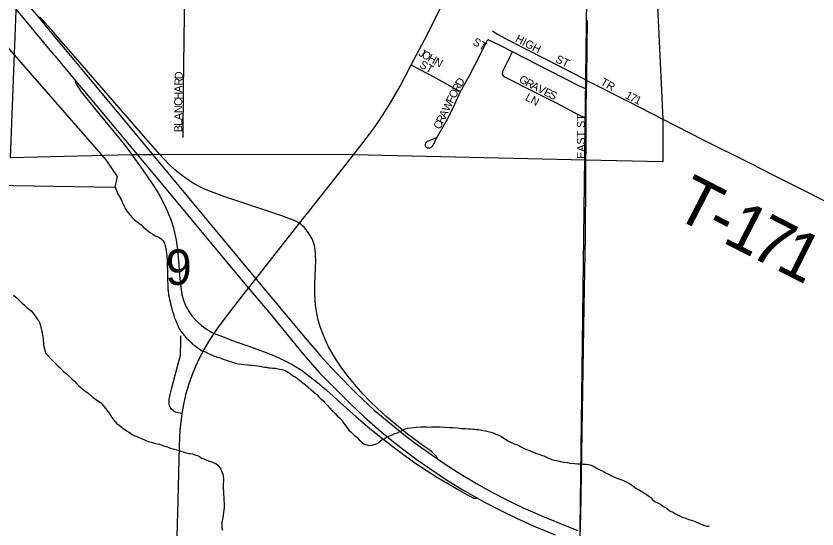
# Model space of a CAD drawing. Extents: x 1587405 to 1714697, y 1028970 to 1155083.
# Drawn here: x 1695136 to 1700142, y 1081711 to 1084915 of the extents above; entities that cross this region are included whole.
import ezdxf

# ---------------------------------------------------------------- set-up
doc = ezdxf.new("R2010")
doc.units = 0
for name, color, linetype in [('GM_X_City_Street', 7, 'Continuous'), ('GM_X_City_Street_Text', 7, 'Continuous'), ('GM_X_Corporation', 7, 'Continuous'), ('GM_X_County_Road', 7, 'Continuous'), ('GM_X_Interchange_Ramps', 7, 'Continuous'), ('GM_X_Minor_Lake', 7, 'Continuous'), ('GM_X_Minor_River', 7, 'Continuous'), ('GM_X_Section', 7, 'Continuous'), ('GM_X_Section_Text', 7, 'Continuous'), ('GM_X_State_Route', 7, 'Continuous'), ('GM_X_Township_Road', 7, 'Continuous'), ('GM_X_Township_Road_Text', 7, 'Continuous')]:
    doc.layers.add(name, color=color, linetype=linetype)

msp = doc.modelspace()

# ---------------------------------------------------------------- linework, layer by layer
at = {"layer": 'GM_X_City_Street'}
for points in [[(1696180.4, 1084157.1), (1696180.5, 1084170.3), (1696182.8, 1084453.8), (1696190.4, 1085080.3), (1696196.4, 1085475.9), (1696195.5, 1085534.4)], [(1698703, 1084513.5), (1698706.2, 1084731.8), (1698708.1, 1084887.9)], [(1698113.1, 1084823), (1698145.8, 1084802.8), (1698217.9, 1084763.1), (1698540.2, 1084598), (1698686.3, 1084522.2), (1698703, 1084513.5)], [(1697914.4, 1084443), (1697967.2, 1084539.1), (1698003.7, 1084609.4), (1698070.2, 1084740.1), (1698085.4, 1084769.4)], [(1698085.4, 1084769.4), (1698159.9, 1084733.1), (1698237.4, 1084693.7)], [(1698237.4, 1084693.7), (1698226.8, 1084668.9), (1698189.4, 1084594.8), (1698176.8, 1084568.6), (1698173.5, 1084552.6), (1698180.3, 1084541.6), (1698192.8, 1084534.1), (1698247.7, 1084506.6), (1698315.5, 1084471.7), (1698508.6, 1084374.4), (1698636.3, 1084305.8), (1698660.9, 1084293.8), (1698677.4, 1084287.3), (1698700.3, 1084283.5)], [(1698237.4, 1084693.7), (1698554.4, 1084532.3), (1698656.4, 1084479.9), (1698671.4, 1084473.2), (1698702.2, 1084459.3)], [(1697606.6, 1084609.6), (1697639.4, 1084592.7), (1697724.8, 1084548.4), (1697888.9, 1084456.7), (1697914.4, 1084443)], [(1698702.2, 1084459.3), (1698703, 1084513.5)], [(1698703, 1084513.5), (1698963.6, 1084380.9), (1699178.9, 1084270.8)], [(1698700.3, 1084283.5), (1698700.4, 1084335.3), (1698702.2, 1084459.3)], [(1697762.4, 1084153.7), (1697726.7, 1084140.2), (1697717.1, 1084136.6), (1697712.2, 1084134.4), (1697707.6, 1084132.2), (1697701.3, 1084128.3), (1697697.5, 1084124.6), (1697694.6, 1084120.1), (1697693.3, 1084115.8), (1697692.9, 1084111.5), (1697693.1, 1084108.8), (1697693.6, 1084105.6), (1697695.3, 1084101.3), (1697697, 1084098.6), (1697698.9, 1084096.9), (1697700.6, 1084095.3), (1697704, 1084093.5), (1697706.6, 1084092.4), (1697709.8, 1084091.8), (1697713.4, 1084091.2), (1697716.8, 1084091.4), (1697720.4, 1084091.8), (1697724, 1084092.9), (1697727.1, 1084094.5), (1697731.2, 1084096.6), (1697734.9, 1084099.3), (1697738.8, 1084103.5), (1697743.9, 1084110.7), (1697748.6, 1084119.5), (1697755.5, 1084134.9), (1697762.4, 1084149.2), (1697804.2, 1084221.4), (1697834.2, 1084275.3), (1697878.9, 1084364.8), (1697914.4, 1084443)], [(1698697.9, 1084015.4), (1698699.6, 1084088.6), (1698700.3, 1084283.5)]]:
    msp.add_lwpolyline(points, dxfattribs=at)
at = {"layer": 'GM_X_Corporation'}
msp.add_lwpolyline([(1695100.6, 1084030), (1695159.1, 1085548.1), (1695169.3, 1086080.7), (1695745, 1086055.9), (1698724.8, 1086009.9), (1699194.3, 1086004.2), (1699195.9, 1085349.8), (1699127.9, 1085331.6), (1699178.9, 1084270.8), (1699178, 1084003.9), (1698697.9, 1084015.4), (1697244.3, 1084048.6), (1696034.7, 1084049.8), (1695991.7, 1084048.9), (1695895, 1084048.9), (1695860.2, 1084049.1)], close=True, dxfattribs=at)
at = {"layer": 'GM_X_County_Road'}
for points in [[(1696156, 1082765.5), (1696159.4, 1082777.6), (1696161.8, 1082786.6), (1696162.9, 1082792.4), (1696163.8, 1082798.2), (1696164.3, 1082804.1), (1696164.5, 1082809.6), (1696164.8, 1082822.1), (1696165.6, 1082865.6), (1696165.9, 1082918.1)], [(1696175.2, 1082432.7), (1696176.9, 1082444.7), (1696188.5, 1082509.4), (1696200.2, 1082557.4), (1696218.8, 1082620.6), (1696240.6, 1082682.8), (1696259.3, 1082728.6), (1696280.3, 1082773.4), (1696311.4, 1082831.5), (1696345.3, 1082888), (1696374.8, 1082932.7)], [(1696175.2, 1082432.7), (1696168.4, 1082433.6), (1696150.1, 1082436), (1696137.6, 1082438.7), (1696132.1, 1082440.7), (1696127.1, 1082443.4), (1696117.1, 1082451), (1696108.4, 1082459.4), (1696100.2, 1082471.9), (1696095.8, 1082483.4), (1696093.5, 1082493.6), (1696092.4, 1082502.4), (1696092.4, 1082510.9), (1696093.8, 1082521.7), (1696095.1, 1082529.7), (1696100, 1082552.1), (1696110.3, 1082593.9), (1696152.2, 1082752.1), (1696156, 1082765.5)], [(1696145.7, 1081751.5), (1696146.7, 1081804.2), (1696157.3, 1082231.4), (1696162.9, 1082330.3), (1696167.9, 1082379.5), (1696175.2, 1082432.7)], [(1696122.9, 1080762.8), (1696130.6, 1081065.7), (1696140, 1081459.5), (1696145.7, 1081751.5)]]:
    msp.add_lwpolyline(points, dxfattribs=at)
at = {"layer": 'GM_X_Interchange_Ramps'}
for points in [[(1696908.4, 1083620.7), (1696884.3, 1083633.6), (1696870, 1083640), (1696852.4, 1083647.3), (1696797.1, 1083668.3), (1696728.6, 1083691), (1696528.9, 1083756.1), (1696435.7, 1083787.8), (1696373.9, 1083810.2), (1696325.2, 1083830), (1696289.5, 1083846.5), (1696248.9, 1083868.1), (1696207.3, 1083894.4), (1696167.5, 1083923.4), (1696129.5, 1083954.8), (1696095.8, 1083986.1), (1696059, 1084023.6), (1696034.7, 1084049.8), (1695948.1, 1084149.9), (1695601.5, 1084548.8), (1695551.8, 1084605.6), (1695418.5, 1084759.3), (1695370.4, 1084814.8), (1695299.6, 1084894), (1695293.2, 1084900.5), (1695289.9, 1084903.5), (1695287.9, 1084904.8), (1695286.3, 1084905.5), (1695285.1, 1084906), (1695283.9, 1084906.3), (1695282.9, 1084906.5), (1695281.6, 1084906.6), (1695279.9, 1084906.6), (1695278.1, 1084906.3)], [(1697769.3, 1082150.1), (1697769.1, 1082152.1), (1697768.7, 1082155.3), (1697768.1, 1082157.4), (1697767.5, 1082159.1), (1697766.9, 1082160.4), (1697766, 1082161.7), (1697765.3, 1082162.8), (1697763.8, 1082164.6), (1697754.5, 1082174.2), (1697742.9, 1082185.2), (1697732.6, 1082194.2), (1697710.1, 1082211.1), (1697691.7, 1082224.5), (1697655.5, 1082249.2), (1697572.7, 1082312.5), (1697511.3, 1082361.8), (1697448.8, 1082414.8), (1697395.3, 1082463.2), (1697348.2, 1082508.8), (1697305.1, 1082553.9), (1697261.7, 1082603), (1697212, 1082664.1), (1697172.7, 1082716.5), (1697139.3, 1082765.3), (1697110, 1082812.7), (1697089.4, 1082850), (1697069.3, 1082891.3), (1697050.6, 1082936.7), (1697037.7, 1082974), (1697025.1, 1083018.1), (1697015.8, 1083059.7), (1697008.1, 1083108.3), (1697004.8, 1083144.1), (1697002.9, 1083180.1), (1697003.8, 1083245.7), (1697007.9, 1083340.8), (1697009.6, 1083383.5), (1697008.7, 1083426.2), (1697006.3, 1083452.2), (1697001, 1083481.2), (1696993.2, 1083506.2), (1696986, 1083524.4), (1696975.3, 1083544.7), (1696962.9, 1083564.1), (1696946.8, 1083584.8), (1696936, 1083596.9), (1696927.4, 1083605.2), (1696914.6, 1083616.5), (1696908.4, 1083620.7)], [(1696374.8, 1082932.7), (1696427.5, 1082912.6), (1696483.5, 1082891.2), (1696573, 1082859), (1696693.4, 1082815.2), (1696760.4, 1082788.5), (1696814.2, 1082764), (1696866.4, 1082736.4), (1696919.4, 1082703.4), (1696974.9, 1082662.6), (1697020.8, 1082625.3), (1697075.8, 1082578.6), (1697262.3, 1082412.8), (1697346.8, 1082339.9), (1697425.5, 1082275.5), (1697490.9, 1082225.8), (1697574.1, 1082164.3), (1697641.8, 1082116.5), (1697771.1, 1082033.6), (1697848.7, 1081986.8), (1697908.9, 1081951.8), (1697963.6, 1081920.9), (1697974.8, 1081915.3), (1697989.6, 1081908), (1697992.4, 1081906.7), (1697995.4, 1081905.3), (1697998.1, 1081904.2), (1698000.8, 1081903.5), (1698003.7, 1081903.2), (1698006.3, 1081903.4), (1698008.5, 1081903.6), (1698011.9, 1081904.3), (1698016.6, 1081905.8)]]:
    msp.add_lwpolyline(points, dxfattribs=at)
at = {"layer": 'GM_X_Minor_Lake'}
for points in [[(1694980.9, 1084838.6), (1694991.3, 1083858), (1695756.4, 1083847)], [(1695756.4, 1083847), (1695769.3, 1083913), (1695698.4, 1084018.1), (1694980.9, 1084838.6)], [(1694980.9, 1084838.6), (1694991.3, 1083858), (1695756.4, 1083847), (1695769.3, 1083913), (1695698.4, 1084018.1), (1694980.9, 1084838.6)]]:
    msp.add_lwpolyline(points, dxfattribs=at)
at = {"layer": 'GM_X_Minor_River'}
for points in [[(1695756.4, 1083847), (1695764.2, 1083824.9), (1695770, 1083806.8), (1695779.8, 1083790.6), (1695787.7, 1083780.5), (1695793.6, 1083770.4), (1695797.5, 1083758.3), (1695803.3, 1083744.2), (1695811.1, 1083730.1), (1695819, 1083713.9), (1695830.7, 1083693.8), (1695846.5, 1083673.5), (1695862.4, 1083657.3), (1695876.2, 1083643.1), (1695894.1, 1083628.9), (1695904, 1083620.7), (1695917.9, 1083610.5), (1695929.8, 1083598.4), (1695945.7, 1083586.1), (1695955.6, 1083578), (1695967.5, 1083567.8), (1695977.4, 1083561.7), (1695991.4, 1083553.5), (1696005.3, 1083543.3), (1696017.2, 1083539.2), (1696029.2, 1083535), (1696043.1, 1083522.8), (1696053, 1083512.7), (1696064.8, 1083496.5), (1696066.7, 1083486.5), (1696070.5, 1083474.4), (1696072.4, 1083460.3), (1696074.3, 1083450.3), (1696077.9, 1083418.2), (1696077.8, 1083408.1), (1696079.6, 1083398.1), (1696081.5, 1083384), (1696081.3, 1083370), (1696081.1, 1083352), (1696082.9, 1083333.9), (1696082.6, 1083311.8), (1696082.3, 1083281.8), (1696082, 1083261.7), (1696083.8, 1083239.6), (1696085.6, 1083221.6), (1696085.4, 1083209.5), (1696087.2, 1083195.5), (1696089.1, 1083181.4), (1696089, 1083171.4), (1696092.8, 1083159.3), (1696094.7, 1083145.3), (1696098.5, 1083129.2), (1696104.3, 1083109.1), (1696108.1, 1083095), (1696111.9, 1083076.9), (1696115.7, 1083064.8), (1696119.6, 1083054.8), (1696125.4, 1083034.6), (1696133.2, 1083018.5), (1696137.1, 1083006.4), (1696142.9, 1082992.3), (1696148.7, 1082976.2), (1696158.5, 1082958.1), (1696166.4, 1082947.9), (1696176.3, 1082933.8), (1696188.1, 1082917.6), (1696202, 1082903.4), (1696215.8, 1082891.2), (1696227.7, 1082879), (1696239.6, 1082864.9), (1696253.5, 1082856.7), (1696265.4, 1082846.5), (1696281.3, 1082836.3), (1696297.2, 1082824.1), (1696321.2, 1082817.8), (1696339.1, 1082807.6), (1696357, 1082799.3), (1696376.9, 1082791.1), (1696394.9, 1082784.8), (1696410.9, 1082780.6), (1696424.8, 1082774.5), (1696468.7, 1082759.9), (1696482.7, 1082755.7), (1696506.6, 1082747.4), (1696524.6, 1082743.2), (1696544.6, 1082741), (1696560.6, 1082738.8), (1696582.6, 1082736.5), (1696598.6, 1082734.3), (1696612.7, 1082734.2), (1696628.7, 1082732), (1696644.7, 1082729.8), (1696662.7, 1082727.6), (1696676.6, 1082723.4), (1696688.6, 1082721.2), (1696700.7, 1082721.1), (1696714.6, 1082718.9), (1696726.7, 1082718.8), (1696738.7, 1082716.6), (1696756.7, 1082716.4), (1696774.7, 1082712.2)], [(1695119.3, 1083170.8), (1695143.1, 1083152.4), (1695157, 1083138.2), (1695172.8, 1083124), (1695188.7, 1083109.8), (1695206.5, 1083093.5), (1695220.4, 1083081.3), (1695232.3, 1083071.2), (1695248.1, 1083052.9), (1695261.9, 1083032.7), (1695269.8, 1083020.6), (1695277.6, 1083010.5), (1695283.5, 1083000.4), (1695287.4, 1082988.3), (1695291.2, 1082972.2), (1695295, 1082954.1), (1695298.8, 1082934.1), (1695304.5, 1082911.9), (1695306.3, 1082891.9), (1695308, 1082869.8), (1695309.8, 1082851.7), (1695313.6, 1082835.6), (1695317.5, 1082821.6), (1695323.3, 1082807.4), (1695335.2, 1082795.3), (1695353, 1082775), (1695396.5, 1082730.4), (1695414.4, 1082716.1), (1695432.2, 1082695.9), (1695452, 1082679.6), (1695469.8, 1082663.4), (1695487.7, 1082647.1), (1695503.5, 1082632.9), (1695515.4, 1082618.7), (1695529.2, 1082604.5), (1695541.1, 1082594.3), (1695555, 1082582.2), (1695568.9, 1082572), (1695584.8, 1082561.8), (1695598.7, 1082549.6), (1695618.5, 1082533.3), (1695634.4, 1082521.1), (1695652.3, 1082508.8), (1695666.2, 1082498.6), (1695680, 1082482.4), (1695695.8, 1082464.2), (1695709.7, 1082446), (1695723.4, 1082425.8), (1695735.2, 1082407.6), (1695747.1, 1082391.4), (1695756.9, 1082379.3), (1695766.8, 1082369.1), (1695778.8, 1082361), (1695790.7, 1082350.8), (1695806.6, 1082338.6), (1695826.4, 1082324.3), (1695844.3, 1082314.1), (1695862.2, 1082301.8), (1695878.1, 1082293.6)], [(1696774.7, 1082712.2), (1696786.7, 1082710.1), (1696798.7, 1082707.9), (1696810.6, 1082703.8), (1696826.6, 1082697.6), (1696836.5, 1082691.4), (1696848.5, 1082683.3), (1696864.3, 1082671), (1696880.2, 1082660.8), (1696896.1, 1082650.6), (1696910, 1082638.4), (1696927.9, 1082624.2), (1696945.8, 1082611.9), (1696961.6, 1082597.7), (1696979.5, 1082581.5), (1696995.3, 1082567.2), (1697015.2, 1082551), (1697029, 1082536.8), (1697040.9, 1082524.6), (1697054.8, 1082514.4), (1697066.6, 1082498.2), (1697082.5, 1082482), (1697098.3, 1082465.8), (1697112.1, 1082449.6), (1697130, 1082433.3), (1697143.8, 1082417.1), (1697157.7, 1082404.9), (1697173.5, 1082388.7), (1697183.4, 1082374.6), (1697216.9, 1082328.1), (1697228.8, 1082317.9), (1697240.6, 1082305.7), (1697252.5, 1082295.6), (1697268.4, 1082283.3), (1697280.2, 1082267.1), (1697290.2, 1082259), (1697302.1, 1082248.8), (1697312, 1082240.7), (1697333.9, 1082234.4), (1697347.9, 1082232.3), (1697362, 1082234.1), (1697382.1, 1082241.9), (1697392.2, 1082245.8), (1697408.3, 1082255.6), (1697424.5, 1082269.5), (1697434.6, 1082273.3), (1697444.7, 1082281.3), (1697456.8, 1082287.1), (1697470.9, 1082293), (1697487, 1082298.8), (1697501.1, 1082306.7), (1697521.2, 1082312.4), (1697535.3, 1082320.3), (1697547.4, 1082326.2), (1697559.5, 1082332), (1697569.6, 1082335.9), (1697585.7, 1082341.8), (1697603.7, 1082343.6), (1697621.8, 1082345.3), (1697639.8, 1082347.1), (1697665.9, 1082348.8), (1697685.9, 1082348.6), (1697701.9, 1082348.4), (1697716, 1082348.2), (1697732, 1082350.1), (1697748, 1082349.9), (1697768.1, 1082349.6), (1697786.1, 1082349.4), (1697846.1, 1082344.7), (1697868.2, 1082344.5), (1697898.2, 1082342.1), (1697918.2, 1082339.9), (1697934.2, 1082339.7), (1697948.3, 1082339.5), (1697964.3, 1082337.3), (1697976.3, 1082337.2), (1697990.3, 1082335), (1698002.3, 1082334.9), (1698014.3, 1082332.7), (1698026.3, 1082332.6), (1698038.3, 1082330.4), (1698056.3, 1082326.2), (1698070.3, 1082324), (1698086.3, 1082319.8), (1698104.2, 1082315.6), (1698118.2, 1082311.4), (1698134.1, 1082303.2), (1698154.1, 1082297), (1698170, 1082288.8), (1698183.9, 1082278.6), (1698197.9, 1082270.4), (1698213.8, 1082260.2), (1698229.7, 1082252), (1698249.6, 1082243.7), (1698263.6, 1082239.6), (1698273.6, 1082235.4), (1698283.6, 1082231.3), (1698293.5, 1082225.2), (1698307.4, 1082217), (1698327.4, 1082208.7), (1698341.3, 1082202.6)], [(1695878.1, 1082293.6), (1695890.1, 1082289.5), (1695900.1, 1082285.4), (1695920, 1082277.1), (1695943.9, 1082266.8), (1695961.9, 1082258.6), (1695981.8, 1082254.3), (1696001.8, 1082248.1), (1696017.8, 1082243.9), (1696031.8, 1082241.7), (1696043.8, 1082237.6), (1696057.7, 1082231.4), (1696071.7, 1082227.2), (1696083.7, 1082225.1), (1696095.6, 1082218.9), (1696109.6, 1082214.7), (1696123.6, 1082210.6), (1696153.5, 1082202.2), (1696165.5, 1082198), (1696181.5, 1082193.8), (1696197.4, 1082187.6), (1696215.4, 1082183.4), (1696227.4, 1082183.3), (1696239.4, 1082181.1), (1696253.4, 1082174.9), (1696269.3, 1082170.7), (1696285.3, 1082162.5), (1696295.2, 1082154.4), (1696305.2, 1082152.3), (1696317.1, 1082146.1), (1696329.1, 1082142), (1696345.1, 1082135.8), (1696359, 1082131.6), (1696369, 1082127.5), (1696385, 1082121.3), (1696396.8, 1082109.1), (1696408.7, 1082096.9), (1696416.6, 1082084.8), (1696422.4, 1082068.7), (1696428.2, 1082054.6), (1696430, 1082038.5), (1696431.9, 1082026.5), (1696431.7, 1082008.4), (1696431.5, 1081994.4), (1696431.4, 1081982.4), (1696431.2, 1081968.3), (1696432.9, 1081940.2), (1696432.7, 1081926.2), (1696434.5, 1081912.1), (1696434.4, 1081902.1), (1696434.3, 1081888.1), (1696436.1, 1081874), (1696435.9, 1081860), (1696437.7, 1081843.9), (1696435.5, 1081827.9), (1696433.4, 1081813.9), (1696431.2, 1081797.9), (1696429, 1081783.9), (1696426.9, 1081771.9), (1696422.6, 1081753.9), (1696422.5, 1081741.9), (1696422.3, 1081729.8), (1696422.2, 1081717.8), (1696426, 1081703.7)], [(1698341.3, 1082202.6), (1698353.2, 1082196.4), (1698367.2, 1082190.2), (1698383.2, 1082184), (1698403.1, 1082177.8), (1698419.1, 1082171.6), (1698435, 1082167.4), (1698447, 1082161.2), (1698458.9, 1082155.1), (1698470.9, 1082150.9), (1698484.9, 1082144.7), (1698500.8, 1082140.5), (1698512.8, 1082138.4), (1698524.8, 1082136.2), (1698538.8, 1082132.1), (1698558.8, 1082127.8), (1698582.8, 1082125.5), (1698596.8, 1082123.4), (1698626.8, 1082121), (1698644.8, 1082118.8), (1698660.9, 1082118.6), (1698678.9, 1082116.4), (1698698.9, 1082116.1), (1698714.9, 1082113.9), (1698730.9, 1082109.7), (1698746.8, 1082101.5), (1698764.7, 1082091.3), (1698784.6, 1082081), (1698804.6, 1082072.8), (1698820.5, 1082062.6), (1698838.4, 1082054.3), (1698854.3, 1082046.1), (1698864.3, 1082042), (1698876.2, 1082035.9), (1698890.2, 1082027.7), (1698916.1, 1082019.3), (1698932.1, 1082013.1), (1698950, 1082004.9), (1698963.9, 1081996.7), (1698981.8, 1081986.5), (1698995.8, 1081978.3), (1699009.6, 1081966.1), (1699025.6, 1081957.9), (1699037.5, 1081951.8), (1699047.5, 1081945.6), (1699059.4, 1081937.5), (1699075.3, 1081929.2), (1699085.2, 1081921.1), (1699095.2, 1081915), (1699103.1, 1081904.9), (1699116.9, 1081890.7), (1699132.8, 1081880.4), (1699150.8, 1081872.2), (1699166.7, 1081864), (1699182.6, 1081851.8), (1699198.5, 1081843.6), (1699210.4, 1081835.4), (1699224.3, 1081823.2), (1699242.3, 1081817), (1699254.2, 1081808.8), (1699270.1, 1081798.6), (1699284, 1081792.5), (1699300, 1081784.2), (1699313.9, 1081780.1), (1699329.9, 1081773.9), (1699341.9, 1081769.7), (1699369.8, 1081761.4), (1699383.8, 1081755.2), (1699399.7, 1081749), (1699417.7, 1081740.8), (1699433.6, 1081734.6), (1699445.6, 1081730.4), (1699455.6, 1081728.3), (1699467.6, 1081726.1), (1699455.6, 1081728.3), (1699467.6, 1081726.1)]]:
    msp.add_lwpolyline(points, dxfattribs=at)
at = {"layer": 'GM_X_Section'}
msp.add_lwpolyline([(1693673.6, 1086101.2), (1698714, 1086017.3), (1698647.4, 1080724.6), (1693579.2, 1080822.9)], close=True, dxfattribs=at)
at = {"layer": 'GM_X_State_Route'}
for points in [[(1697244.3, 1084048.6), (1697311.7, 1084134.2), (1697380.4, 1084226.1), (1697427.1, 1084293.7), (1697470.6, 1084363.3), (1697536, 1084477), (1697606.6, 1084609.6), (1697688, 1084767), (1697770.2, 1084927.7), (1697785.5, 1084957.5), (1697792.3, 1084970.8), (1697802.1, 1084989.9), (1697829.4, 1085043.6), (1697839.9, 1085064), (1697889, 1085159.9), (1697930.5, 1085237.6)], [(1695136.6, 1084957.2), (1695369.1, 1084677.8), (1695380.6, 1084664.1), (1695510.5, 1084508.2), (1695641.5, 1084352), (1695895, 1084048.9)], [(1695221, 1084972.9), (1695278.1, 1084906.3), (1695368.8, 1084795), (1695442.7, 1084706.8), (1695598.8, 1084518.7), (1695799.5, 1084280), (1695991.7, 1084048.9), (1696635.7, 1083274.5), (1696943.3, 1082904.6), (1697039.3, 1082792.2), (1697127.7, 1082694.9), (1697267.3, 1082553.5), (1697375.2, 1082454.4), (1697478, 1082367.8), (1697560.2, 1082302.4), (1697630.7, 1082248), (1697693.4, 1082203.1), (1697769.3, 1082150.1), (1697819.1, 1082116.1), (1697915.9, 1082053.9), (1698014.5, 1081994.7), (1698115, 1081938.7), (1698202.7, 1081893.5), (1698306.6, 1081844.1), (1698426.9, 1081791.2), (1698579, 1081729.2), (1698648.3, 1081702.5)], [(1695510.5, 1084508.2), (1695509.6, 1084507.1), (1695509.1, 1084506.3), (1695508.6, 1084505.3), (1695508.4, 1084504.5), (1695508.3, 1084503.5), (1695508.3, 1084502), (1695508.4, 1084500.4), (1695508.6, 1084499.1), (1695508.9, 1084497.1), (1695509.6, 1084494.9), (1695511, 1084491.6), (1695513.5, 1084486.8), (1695543.4, 1084441.9), (1695579, 1084397.9), (1695632.6, 1084331.6), (1695750, 1084190.4), (1695813.4, 1084110.9), (1695859, 1084050.8), (1695860.2, 1084049.1)], [(1695860.2, 1084049.1), (1695910.8, 1083979), (1695954, 1083917.2), (1695989, 1083865.5), (1696023.9, 1083810), (1696051.1, 1083761.4), (1696073.1, 1083717.4), (1696087.7, 1083684.4), (1696105.3, 1083638.5), (1696120, 1083591.5), (1696129.5, 1083553.4), (1696137.5, 1083514.9), (1696145.7, 1083456.5), (1696151.8, 1083384.6), (1696159.6, 1083273.3), (1696167.5, 1083204.9), (1696173, 1083175.9), (1696181.9, 1083141.1), (1696194.1, 1083110.7), (1696202.6, 1083093), (1696217.9, 1083067.7), (1696234.9, 1083043.7), (1696253.9, 1083021.1), (1696272.3, 1083002.4), (1696294.5, 1082983), (1696323.5, 1082962.1), (1696351.1, 1082944.6), (1696362, 1082939.1), (1696374.8, 1082932.7)], [(1695895, 1084048.9), (1695958.6, 1083972.8), (1696137.7, 1083758.9), (1696420.5, 1083417.8), (1696589.8, 1083215.7), (1696717.6, 1083063.3), (1696921.6, 1082813.6), (1697030.9, 1082689.7), (1697135.3, 1082583.8), (1697228.3, 1082490.8), (1697311.5, 1082410.9), (1697398.8, 1082335.2), (1697474, 1082271.9), (1697551.1, 1082211), (1697643.5, 1082142.9), (1697722.1, 1082088.1), (1697820.6, 1082023.1), (1697871.1, 1081990.7), (1697929.2, 1081955.5), (1698016.6, 1081905.8), (1698059.6, 1081881.6), (1698161.3, 1081828.4), (1698264.5, 1081778.3), (1698369.1, 1081731.3), (1698505.5, 1081675.1)], [(1696374.8, 1082932.7), (1696390.7, 1082956.6), (1696449, 1083036.2), (1696570.2, 1083191.6), (1696589.8, 1083215.7), (1696635.7, 1083274.5), (1696908.4, 1083620.7), (1696966, 1083694.7), (1697138.5, 1083913.9), (1697244.3, 1084048.6)]]:
    msp.add_lwpolyline(points, dxfattribs=at)
at = {"layer": 'GM_X_Township_Road'}
for points in [[(1699178.9, 1084270.8), (1699430.3, 1084142.3), (1699723.5, 1083996.2), (1699869.5, 1083921.7), (1700074.7, 1083819.3), (1700250, 1083730.3), (1700601.5, 1083553.9), (1700879.2, 1083413.3), (1701291.1, 1083205.1)], [(1698664, 1081696.5), (1698664.7, 1081741.5), (1698666.3, 1081790.7), (1698686.3, 1083101.3), (1698694.7, 1083542.3), (1698697.4, 1083900.3), (1698697.9, 1084015.4)]]:
    msp.add_lwpolyline(points, dxfattribs=at)

# ---------------------------------------------------------------- texts
at = {"layer": 'GM_X_City_Street_Text'}
for s, rotation, p in [('ST', 330.2568, (1697985.5, 1084740)), ('HIGH', 332.7037, (1698252.2, 1084757.7)), ('J', 330.0329, (1697647.7, 1084671.2)), ('O', 330.0261, (1697666.8, 1084660.2)), ('H', 330.046, (1697704.9, 1084638.2)), ('N', 331.3453, (1697744.1, 1084615.6)), ('ST', 333.435, (1698502.9, 1084630.2)), ('ST', 330.2568, (1697653.2, 1084597.5)), ('D', 87.8797, (1696177.3, 1084520)), ('R', 87.9112, (1696175.9, 1084480.4)), ('D', 59.6098, (1697919.6, 1084470.2)), ('G', 329.5422, (1698274.8, 1084506.5)), ('R', 332.3044, (1698315.1, 1084483)), ('TR', 330.6435, (1698784.9, 1084489.1)), ('A', 88.776, (1696174.9, 1084436.7)), ('O', 63.6109, (1697881.3, 1084396.9)), ('R', 61.0232, (1697900.6, 1084435.8)), ('A', 333.4198, (1698351.1, 1084464.1)), ('V', 333.4347, (1698390.4, 1084444.4)), ('E', 333.4534, (1698429.8, 1084424.7)), ('H', 89.9781, (1696174.9, 1084392.9)), ('F', 63.826, (1697865.8, 1084365.4)), ('LN', 332.1033, (1698313.7, 1084392)), ('S', 333.435, (1698461.3, 1084408.9)), ('1', 331.2699, (1698939.1, 1084405.3)), ('7', 334.1003, (1698968.5, 1084389.3)), ('1', 334.9386, (1698997, 1084375.5)), ('C', 89.994, (1696174.9, 1084353.3)), ('N', 89.9781, (1696174.9, 1084309.3)), ('W', 63.826, (1697840.6, 1084314)), ('A', 89.9928, (1696174.9, 1084265.3)), ('A', 63.8428, (1697821.2, 1084274.6)), ('L', 89.9727, (1696174.9, 1084230.1)), ('C', 63.8369, (1697786.2, 1084203.5)), ('R', 63.8151, (1697803.7, 1084239)), ('EAST ST', 90, (1698691.7, 1084023.3)), ('B', 90, (1696174.9, 1084190.5))]:
    msp.add_text(s, height=50, rotation=rotation, dxfattribs=at).set_placement(p)
at = {"layer": 'GM_X_Section_Text'}
msp.add_text('9', height=221, rotation=0, dxfattribs=at).set_placement((1696069.9, 1083236.1))
at = {"layer": 'GM_X_Township_Road_Text'}
for s, rotation, p in [('T', 332.791, (1699233, 1083665.9)), ('1', 332.8232, (1699542.3, 1083506.9)), ('-', 332.8021, (1699432.6, 1083563.2)), ('7', 332.9148, (1699707.2, 1083422.2)), ('1', 333.2846, (1699873.6, 1083337.1))]:
    msp.add_text(s, height=300, rotation=rotation, dxfattribs=at).set_placement(p)

doc.saveas('drawing.dxf')
